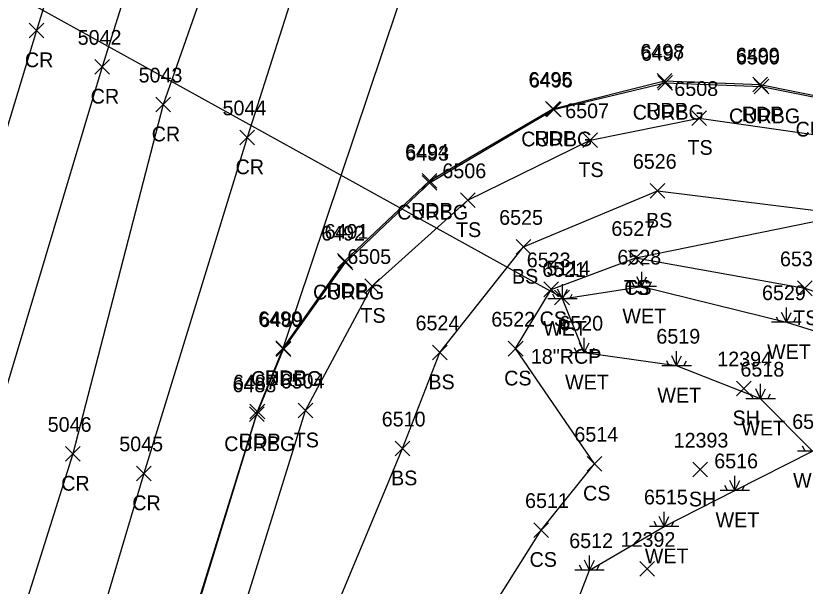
# Model space of a CAD drawing. Extents: x 1462089 to 1464015, y 730534 to 736144.
# Drawn here: x 1462645.7 to 1462752.9, y 731510.2 to 731587.7 of the extents above; entities that cross this region are included whole.
import ezdxf

# ---------------------------------------------------------------- set-up
doc = ezdxf.new("R2010")
doc.units = 0
for name, color, linetype in [('D_A', 7, 'Continuous'), ('D_C', 7, 'Continuous'), ('D_I', 7, 'Continuous'), ('D_TIC', 7, 'Continuous'), ('DCP', 7, 'Continuous'), ('L_A', 7, 'Continuous'), ('L_I', 7, 'Continuous'), ('L_TIC', 7, 'Continuous'), ('LELB', 7, 'Continuous'), ('LWET', 7, 'Continuous'), ('P_A', 7, 'Continuous'), ('P_I', 7, 'Continuous'), ('P_TIC', 7, 'Continuous'), ('PET', 7, 'Continuous'), ('PRC', 7, 'Continuous'), ('R_A', 7, 'Continuous'), ('R_I', 7, 'Continuous'), ('R_TIC', 7, 'Continuous'), ('RC', 7, 'Continuous')]:
    doc.layers.add(name, color=color, linetype=linetype)

msp = doc.modelspace()

# ---------------------------------------------------------------- linework, layer by layer
at = {"layer": 'D_TIC'}
for points in [[(1462718.88, 731548.46), (1462720.88, 731550.46)], [(1462720.88, 731548.46), (1462718.88, 731550.46)]]:
    msp.add_lwpolyline(points, dxfattribs=at)
at = {"layer": 'DCP'}
msp.add_lwpolyline([(1462628.33, 731600.13), (1462719.88, 731549.46)], dxfattribs=at)
at = {"layer": 'L_TIC'}
for points in [[(1462737.52, 731572.85), (1462739.52, 731574.85)], [(1462739.52, 731572.85), (1462737.52, 731574.85)], [(1462722.7, 731569.83), (1462724.7, 731571.83)], [(1462724.7, 731569.83), (1462722.7, 731571.83)], [(1462731.86, 731562.96), (1462733.86, 731564.96)], [(1462733.86, 731562.96), (1462731.86, 731564.96)], [(1462706.07, 731561.68), (1462708.07, 731563.68)], [(1462708.07, 731561.68), (1462706.07, 731563.68)], [(1462713.64, 731555.34), (1462715.64, 731557.34)], [(1462715.64, 731555.34), (1462713.64, 731557.34)], [(1462728.89, 731553.83), (1462730.89, 731555.83)], [(1462730.89, 731553.83), (1462728.89, 731555.83)], [(1462728.89, 731553.83), (1462730.89, 731555.83)], [(1462730.89, 731553.83), (1462728.89, 731555.83)], [(1462693.09, 731550.02), (1462695.09, 731552.02)], [(1462695.09, 731550.02), (1462693.09, 731552.02)], [(1462717.4, 731549.57), (1462719.4, 731551.57)], [(1462719.4, 731549.57), (1462717.4, 731551.57)], [(1462751.88, 731549.71), (1462753.88, 731551.71)], [(1462753.88, 731549.71), (1462751.88, 731551.71)], [(1462702.29, 731541), (1462704.29, 731543)], [(1462704.29, 731541), (1462702.29, 731543)], [(1462712.58, 731541.51), (1462714.58, 731543.51)], [(1462714.58, 731541.51), (1462712.58, 731543.51)], [(1462743.57, 731536.1), (1462745.57, 731538.1)], [(1462745.57, 731536.1), (1462743.57, 731538.1)], [(1462684.03, 731533.1), (1462686.03, 731535.1)], [(1462686.03, 731533.1), (1462684.03, 731535.1)], [(1462697.22, 731527.94), (1462699.22, 731529.94)], [(1462699.22, 731527.94), (1462697.22, 731529.94)], [(1462723.3, 731525.87), (1462725.3, 731527.87)], [(1462725.3, 731525.87), (1462723.3, 731527.87)], [(1462737.63, 731525.07), (1462739.63, 731527.07)], [(1462739.63, 731525.07), (1462737.63, 731527.07)], [(1462716.03, 731516.86), (1462718.03, 731518.86)], [(1462718.03, 731516.86), (1462716.03, 731518.86)], [(1462730.43, 731511.58), (1462732.43, 731513.58)], [(1462732.43, 731511.58), (1462730.43, 731513.58)]]:
    msp.add_lwpolyline(points, dxfattribs=at)
at = {"layer": 'LELB'}
for points in [[(1462725.83, 731477.73), (1462699.03, 731484.88), (1462678.02, 731490.51), (1462672.21, 731492.87), (1462685.03, 731534.1), (1462694.09, 731551.02), (1462707.07, 731562.68), (1462723.7, 731570.83), (1462738.52, 731573.85), (1462757.84, 731571.09), (1462803.89, 731553.92), (1462852.61, 731535.53), (1462892.59, 731519.26), (1462943.53, 731500), (1462989.56, 731482.33), (1463038.41, 731464.73), (1463096.36, 731442.72), (1463144.39, 731425.15), (1463184.91, 731409.31), (1463228.27, 731391.66), (1463272.85, 731369.67), (1463317.31, 731351.5), (1463360.65, 731325.78), (1463401.48, 731298.99)], [(1462704.46, 731497.81), (1462686.16, 731500.02), (1462698.22, 731528.94), (1462703.29, 731542), (1462714.64, 731556.34), (1462732.86, 731563.96), (1462758.79, 731560.72), (1462800.62, 731547.77), (1462850.71, 731531.04), (1462891.22, 731514), (1462941.79, 731496.05), (1462986.9, 731476.74), (1463039.19, 731460.33), (1463094.46, 731438.38), (1463142.72, 731421.22), (1463180.95, 731402.04), (1463225.03, 731385.65), (1463269.42, 731363.58), (1463313.96, 731345.04), (1463357.55, 731320.57), (1463397.02, 731291.85), (1463445.25, 731256.26)], [(1462699.03, 731484.88), (1462704.46, 731497.81), (1462717.03, 731517.86), (1462724.3, 731526.87), (1462713.58, 731542.51), (1462718.4, 731550.57), (1462729.89, 731554.83), (1462758.79, 731560.72)], [(1462729.89, 731554.83), (1462752.88, 731550.71), (1462796.34, 731535.84), (1462846.87, 731523.3), (1462891.6, 731504.38), (1462938.92, 731483.15), (1462981.55, 731463.36), (1463030.83, 731437.13), (1463081.03, 731412.21)]]:
    msp.add_lwpolyline(points, dxfattribs=at)
at = {"layer": 'LWET'}
for p, q in [((1462730.7, 731550.95), (1462730.7, 731552.95)), ((1462729.7, 731550.95), (1462729.37, 731551.62)), ((1462730.7, 731550.95), (1462730.04, 731552.29)), ((1462730.7, 731550.95), (1462731.37, 731552.29)), ((1462731.7, 731550.95), (1462732.04, 731551.62)), ((1462719.94, 731549.27), (1462719.27, 731550.6)), ((1462719.94, 731549.27), (1462719.94, 731551.27)), ((1462719.94, 731549.27), (1462720.61, 731550.6)), ((1462732.7, 731550.95), (1462728.7, 731550.95)), ((1462721.94, 731549.27), (1462717.94, 731549.27)), ((1462718.94, 731549.27), (1462718.61, 731549.93)), ((1462720.94, 731549.27), (1462721.27, 731549.93)), ((1462750.36, 731546.11), (1462749.7, 731547.44)), ((1462750.36, 731546.11), (1462750.36, 731548.11)), ((1462750.36, 731546.11), (1462751.03, 731547.44)), ((1462752.36, 731546.11), (1462748.36, 731546.11)), ((1462749.36, 731546.11), (1462749.03, 731546.77)), ((1462751.36, 731546.11), (1462751.7, 731546.77)), ((1462722.91, 731541.96), (1462722.91, 731543.96)), ((1462722.91, 731541.96), (1462722.24, 731543.29)), ((1462722.91, 731541.96), (1462723.57, 731543.29)), ((1462724.91, 731541.96), (1462720.91, 731541.96)), ((1462721.91, 731541.96), (1462721.57, 731542.62)), ((1462723.91, 731541.96), (1462724.24, 731542.62)), ((1462735.45, 731540.19), (1462735.45, 731542.19)), ((1462734.45, 731540.19), (1462734.12, 731540.86)), ((1462735.45, 731540.19), (1462734.78, 731541.53)), ((1462735.45, 731540.19), (1462736.12, 731541.53)), ((1462736.45, 731540.19), (1462736.78, 731540.86)), ((1462737.45, 731540.19), (1462733.45, 731540.19)), ((1462746.86, 731535.71), (1462746.86, 731537.71)), ((1462745.86, 731535.71), (1462745.53, 731536.38)), ((1462746.86, 731535.71), (1462746.19, 731537.04)), ((1462746.86, 731535.71), (1462747.53, 731537.04)), ((1462747.86, 731535.71), (1462748.19, 731536.38)), ((1462748.86, 731535.71), (1462744.86, 731535.71)), ((1462752.89, 731528.6), (1462752.55, 731529.27)), ((1462755.89, 731528.6), (1462751.89, 731528.6)), ((1462743.36, 731523.25), (1462742.69, 731524.58)), ((1462743.36, 731523.25), (1462743.36, 731525.25)), ((1462743.36, 731523.25), (1462744.02, 731524.58)), ((1462742.36, 731523.25), (1462742.02, 731523.91)), ((1462744.36, 731523.25), (1462744.69, 731523.91)), ((1462745.36, 731523.25), (1462741.36, 731523.25)), ((1462733.75, 731518.35), (1462733.75, 731520.35)), ((1462733.75, 731518.35), (1462733.08, 731519.68)), ((1462733.75, 731518.35), (1462734.41, 731519.68)), ((1462735.75, 731518.35), (1462731.75, 731518.35)), ((1462732.75, 731518.35), (1462732.41, 731519.02)), ((1462734.75, 731518.35), (1462735.08, 731519.02)), ((1462723.6, 731512.41), (1462723.6, 731514.41)), ((1462722.6, 731512.41), (1462722.27, 731513.08)), ((1462723.6, 731512.41), (1462722.94, 731513.75)), ((1462723.6, 731512.41), (1462724.27, 731513.75)), ((1462724.6, 731512.41), (1462724.94, 731513.08)), ((1462725.6, 731512.41), (1462721.6, 731512.41))]:
    msp.add_line(p, q, dxfattribs=at)
msp.add_lwpolyline([(1462733.57, 731494.55), (1462725.26, 731500.55), (1462719.94, 731502.96), (1462723.6, 731512.41), (1462733.75, 731518.35), (1462743.36, 731523.25), (1462753.89, 731528.6), (1462746.86, 731535.71), (1462735.45, 731540.19), (1462722.91, 731541.96), (1462719.94, 731549.27), (1462730.7, 731550.95), (1462750.36, 731546.11), (1462796.24, 731531.79), (1462845.76, 731520.14), (1462890.22, 731497.14), (1462935.58, 731479.91), (1462979.84, 731458.59), (1463028.53, 731430.07), (1463078.39, 731408.92), (1463133.15, 731393.57), (1463171.56, 731375.44), (1463214.42, 731357.49), (1463259.4, 731337.33)], dxfattribs=at)
at = {"layer": 'P_TIC'}
for points in [[(1462647.47, 731584.76), (1462649.47, 731586.76)], [(1462649.47, 731584.76), (1462647.47, 731586.76)], [(1462656.42, 731579.81), (1462658.42, 731581.81)], [(1462658.42, 731579.81), (1462656.42, 731581.81)], [(1462732.82, 731577.91), (1462734.82, 731579.91)], [(1462734.82, 731577.91), (1462732.82, 731579.91)], [(1462745.81, 731577.39), (1462747.81, 731579.39)], [(1462747.81, 731577.39), (1462745.81, 731579.39)], [(1462664.7, 731574.68), (1462666.7, 731576.68)], [(1462666.7, 731574.68), (1462664.7, 731576.68)], [(1462717.63, 731574.1), (1462719.63, 731576.1)], [(1462719.63, 731574.1), (1462717.63, 731576.1)], [(1462676.1, 731570.22), (1462678.1, 731572.22)], [(1462678.1, 731570.22), (1462676.1, 731572.22)], [(1462700.87, 731564.32), (1462702.87, 731566.32)], [(1462702.87, 731564.32), (1462700.87, 731566.32)], [(1462689.37, 731553.44), (1462691.37, 731555.44)], [(1462691.37, 731553.44), (1462689.37, 731555.44)], [(1462681, 731541.57), (1462683, 731543.57)], [(1462683, 731541.57), (1462681, 731543.57)], [(1462681, 731541.57), (1462683, 731543.57)], [(1462683, 731541.57), (1462681, 731543.57)], [(1462677.49, 731532.96), (1462679.49, 731534.96)], [(1462679.49, 731532.96), (1462677.49, 731534.96)], [(1462652.41, 731527.21), (1462654.41, 731529.21)], [(1462654.41, 731527.21), (1462652.41, 731529.21)], [(1462662.07, 731524.56), (1462664.07, 731526.56)], [(1462664.07, 731524.56), (1462662.07, 731526.56)]]:
    msp.add_lwpolyline(points, dxfattribs=at)
at = {"layer": 'PET'}
for points in [[(1462581.47, 731216.16), (1462595.42, 731259.35), (1462601.33, 731282.14), (1462611.9, 731313.3), (1462617.75, 731332.74), (1462626.73, 731363.12), (1462635.96, 731395.2), (1462650.7, 731443.13), (1462658.25, 731467.85), (1462666.38, 731494.9), (1462678.49, 731533.96), (1462682, 731542.57), (1462703.33, 731606.12), (1462712.89, 731635.26), (1462724.51, 731674.81), (1462732.57, 731701.31), (1462734.12, 731706.18), (1462734.47, 731705.73), (1462745.24, 731743.48), (1462759.09, 731789.57)], [(1462682, 731542.57), (1462690.37, 731554.44), (1462701.87, 731565.32), (1462718.63, 731575.1), (1462733.82, 731578.91), (1462746.81, 731578.39), (1462756.2, 731576.5), (1462761.65, 731574.84), (1462805.91, 731559.14), (1462855.47, 731540.72), (1462896.06, 731525.28), (1462946.06, 731505.97), (1462992.04, 731488.44), (1463040, 731470.15), (1463098.6, 731447.89), (1463146.47, 731429.53), (1463186.4, 731413.97), (1463230.08, 731397.45), (1463276.87, 731377.97), (1463320.08, 731356.26), (1463363.63, 731330.24), (1463405.12, 731302.86), (1463454, 731267.4)]]:
    msp.add_lwpolyline(points, dxfattribs=at)
at = {"layer": 'PRC'}
for points in [[(1462761.02, 731958.42), (1462747.81, 731917.01), (1462738.76, 731883.17), (1462729.11, 731854.95), (1462715.07, 731806.48), (1462712.12, 731796.98), (1462698.11, 731749.33), (1462686.28, 731711.96), (1462673.04, 731665.23), (1462661.99, 731629.57), (1462648.47, 731585.76), (1462633.36, 731535.92), (1462617.82, 731486.9), (1462603.28, 731439.32), (1462592.21, 731404.81), (1462578.75, 731359.84), (1462563.85, 731311.63), (1462546.16, 731252.05), (1462529.31, 731193.32), (1462512.83, 731138.46), (1462500.46, 731089.18), (1462489.91, 731049.97), (1462473.45, 730997.55), (1462460.79, 730938.78)], [(1462772.41, 731954.34), (1462759.38, 731913.09), (1462748.7, 731879.95), (1462739.42, 731851.91), (1462725.15, 731803.68), (1462721.86, 731793.61), (1462708.1, 731747.06), (1462696.47, 731709.22), (1462683.6, 731662.38), (1462671.41, 731625.3), (1462657.42, 731580.81), (1462643.06, 731532.94), (1462627.44, 731482.74), (1462613.37, 731434.9), (1462602.35, 731399.64), (1462589.57, 731355.87), (1462573.75, 731306.68), (1462555.88, 731246.43), (1462538.49, 731188.95), (1462522.11, 731136.27), (1462509.01, 731086.5)], [(1462782.02, 731950.47), (1462768.89, 731909.84), (1462760.03, 731877.27), (1462749.82, 731847.72), (1462735.79, 731799.64), (1462732.29, 731789.16), (1462718.71, 731743.61), (1462707.11, 731705.53), (1462694.32, 731660.71), (1462680.69, 731618.48), (1462665.7, 731575.68), (1462653.41, 731528.21), (1462637.72, 731478.42), (1462624.25, 731431.84), (1462612.57, 731394.54), (1462600.92, 731353.76), (1462584.46, 731303.13), (1462565.79, 731242.26), (1462548.64, 731186.3), (1462531.51, 731132.98), (1462517.28, 731085.28)], [(1462793.02, 731947.65), (1462779.18, 731905.95), (1462772.13, 731874.55), (1462759.59, 731843.4), (1462745.8, 731796.52), (1462742.09, 731785.85), (1462729.2, 731739.31), (1462722.15, 731715.56), (1462711.04, 731679.92), (1462704.9, 731658.03), (1462690.28, 731612.58), (1462677.1, 731571.22), (1462663.07, 731525.56), (1462648.8, 731477.5), (1462634.52, 731430.68), (1462623.14, 731390.72), (1462610.92, 731351.23), (1462594.7, 731298.49), (1462575.73, 731238.98), (1462558.6, 731184.66), (1462539.6, 731135.54), (1462521.54, 731083.73), (1462509.35, 731045.03)]]:
    msp.add_lwpolyline(points, dxfattribs=at)
at = {"layer": 'R_TIC'}
for points in [[(1462732.91, 731577.63), (1462734.91, 731579.63)], [(1462734.91, 731577.63), (1462732.91, 731579.63)], [(1462745.98, 731577.14), (1462747.98, 731579.14)], [(1462747.98, 731577.14), (1462745.98, 731579.14)], [(1462717.75, 731574), (1462719.75, 731576)], [(1462719.75, 731574), (1462717.75, 731576)], [(1462700.89, 731564.06), (1462702.89, 731566.06)], [(1462702.89, 731564.06), (1462700.89, 731566.06)], [(1462689.48, 731553.2), (1462691.48, 731555.2)], [(1462691.48, 731553.2), (1462689.48, 731555.2)], [(1462681.05, 731541.45), (1462683.05, 731543.45)], [(1462683.05, 731541.45), (1462681.05, 731543.45)], [(1462677.41, 731532.59), (1462679.41, 731534.59)], [(1462679.41, 731532.59), (1462677.41, 731534.59)]]:
    msp.add_lwpolyline(points, dxfattribs=at)
at = {"layer": 'RC'}
msp.add_lwpolyline([(1462651.17, 731439.34), (1462650.96, 731442.96), (1462658.42, 731467.75), (1462666.56, 731494.97), (1462678.41, 731533.59), (1462682.05, 731542.45), (1462690.48, 731554.2), (1462701.89, 731565.06), (1462718.75, 731575), (1462733.91, 731578.63), (1462746.98, 731578.14), (1462756.03, 731576.34), (1462761.65, 731574.84)], dxfattribs=at)

# ---------------------------------------------------------------- texts
at = {"layer": 'D_A'}
msp.add_text('P', height=2, dxfattribs=at).set_placement((1462719.26, 731544.46))
at = {"layer": 'D_C'}
msp.add_text('18"RCP', height=2, dxfattribs=at).set_placement((1462715.65, 731540.46))
at = {"layer": 'D_I'}
msp.add_text('5114', height=2, dxfattribs=at).set_placement((1462717.76, 731552.46))
at = {"layer": 'L_A'}
for s, p in [('TS', (1462736.93, 731568.85)), ('TS', (1462722.11, 731565.83)), ('BS', (1462731.3, 731558.96)), ('TS', (1462705.48, 731557.68)), ('BS', (1462713.08, 731551.34)), ('TS', (1462728.3, 731549.83)), ('CS', (1462728.33, 731549.83)), ('TS', (1462692.5, 731546.02)), ('CS', (1462716.84, 731545.57)), ('WET', (1462728.08, 731545.95)), ('TS', (1462751.29, 731545.71)), ('WET', (1462717.32, 731544.27)), ('WET', (1462747.74, 731541.11)), ('BS', (1462701.73, 731537)), ('CS', (1462712.02, 731537.51)), ('WET', (1462720.29, 731536.96)), ('WET', (1462732.83, 731535.19)), ('SH', (1462743.05, 731532.1)), ('WET', (1462744.24, 731530.71)), ('TS', (1462683.44, 731529.1)), ('BS', (1462696.66, 731523.94)), ('WET', (1462751.27, 731523.6)), ('CS', (1462722.74, 731521.87)), ('SH', (1462737.12, 731521.07)), ('WET', (1462740.74, 731518.25)), ('WET', (1462731.13, 731513.35)), ('CS', (1462715.47, 731512.86))]:
    msp.add_text(s, height=2, dxfattribs=at).set_placement(p)
at = {"layer": 'L_I'}
for s, p in [('6508', (1462735.14, 731576.85)), ('6507', (1462720.31, 731573.83)), ('6526', (1462729.5, 731566.96)), ('6506', (1462703.63, 731565.68)), ('6525', (1462711.34, 731559.34)), ('6527', (1462726.58, 731557.83)), ('6527', (1462726.58, 731557.83)), ('6505', (1462690.71, 731554.02)), ('6528', (1462727.4, 731553.95)), ('6530', (1462749.49, 731553.71)), ('6523', (1462715.09, 731553.57)), ('6521', (1462717.2, 731552.27)), ('6529', (1462747.05, 731549.11)), ('6522', (1462710.27, 731545.51)), ('6524', (1462699.98, 731545)), ('6520', (1462719.51, 731544.96)), ('6519', (1462732.7, 731543.19)), ('12394', (1462740.97, 731540.1)), ('6518', (1462744.12, 731538.71)), ('6504', (1462681.65, 731537.1)), ('6510', (1462695.39, 731531.94)), ('6517', (1462751.15, 731531.6)), ('6514', (1462721.56, 731529.87)), ('12393', (1462735.04, 731529.07)), ('6516', (1462740.56, 731526.25)), ('6511', (1462714.86, 731520.86)), ('6515', (1462731.01, 731521.35)), ('6512', (1462720.86, 731515.41)), ('12392', (1462727.84, 731515.58))]:
    msp.add_text(s, height=2, dxfattribs=at).set_placement(p)
at = {"layer": 'P_A'}
for s, p in [('CR', (1462646.91, 731580.76)), ('CR', (1462655.85, 731575.81)), ('RDP', (1462731.31, 731573.91)), ('RDP', (1462744.3, 731573.39)), ('CR', (1462664.14, 731570.68)), ('RDP', (1462716.11, 731570.1)), ('CR', (1462675.53, 731566.22)), ('RDP', (1462699.36, 731560.32)), ('RDP', (1462687.86, 731549.44)), ('RDP', (1462679.49, 731537.57)), ('RDP', (1462679.49, 731537.57)), ('RDP', (1462675.98, 731528.96)), ('CR', (1462651.84, 731523.21)), ('CR', (1462661.5, 731520.56))]:
    msp.add_text(s, height=2, dxfattribs=at).set_placement(p)
at = {"layer": 'P_I'}
for s, p in [('5042', (1462654.08, 731583.81)), ('6498', (1462730.51, 731581.91)), ('6499', (1462743.5, 731581.39)), ('5043', (1462662.36, 731578.68)), ('6495', (1462715.32, 731578.1)), ('5044', (1462673.76, 731574.22)), ('6494', (1462698.56, 731568.32)), ('6491', (1462687.63, 731557.44)), ('6490', (1462678.61, 731545.57)), ('6490', (1462678.61, 731545.57)), ('6487', (1462675.19, 731536.96)), ('5046', (1462650.01, 731531.21)), ('5045', (1462659.73, 731528.56))]:
    msp.add_text(s, height=2, dxfattribs=at).set_placement(p)
at = {"layer": 'R_A'}
for p in [(1462729.49, 731573.63), (1462742.57, 731573.14), (1462751.61, 731571.34), (1462714.34, 731570), (1462697.47, 731560.06), (1462686.06, 731549.2), (1462677.63, 731537.45), (1462673.99, 731528.59)]:
    msp.add_text('CURBG', height=2, dxfattribs=at).set_placement(p)
at = {"layer": 'R_I'}
for s, p in [('6497', (1462730.6, 731581.63)), ('6500', (1462743.51, 731581.14)), ('6496', (1462715.39, 731578)), ('6493', (1462698.58, 731568.06)), ('6492', (1462687.17, 731557.2)), ('6489', (1462678.74, 731545.45)), ('6488', (1462675.11, 731536.59))]:
    msp.add_text(s, height=2, dxfattribs=at).set_placement(p)

doc.saveas('drawing.dxf')
